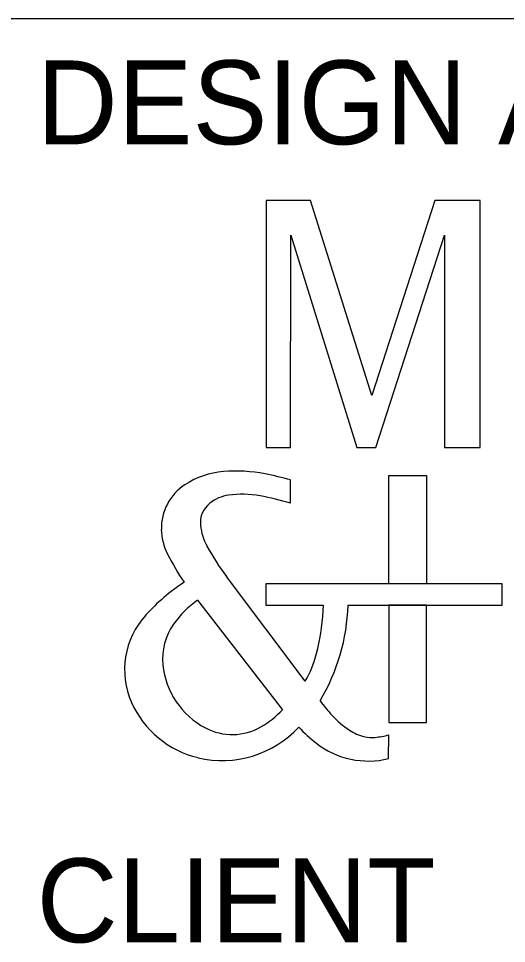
# Model space of a CAD drawing. Extents: x 0 to 34, y 0 to 22.
# Drawn here: x 32.028 to 32.61, y 3.397 to 4.5 of the extents above; entities that cross this region are included whole.
import ezdxf

# ---------------------------------------------------------------- set-up
doc = ezdxf.new("R2010")
doc.units = 0
for name, color, linetype in [('SH_Border', 7, 'Continuous'), ('SH_Data', 7, 'Continuous'), ('SH_Text', 7, 'Continuous')]:
    doc.layers.add(name, color=color, linetype=linetype)

msp = doc.modelspace()

# ---------------------------------------------------------------- linework, layer by layer
at = {"layer": 'SH_Border'}
msp.add_line((32, 4.5), (33.5, 4.5), dxfattribs=at)
at = {"layer": 'SH_Data'}
for p, q in [((32.3525, 3.922), (32.3525, 3.9497)), ((32.4696, 3.8261), (32.4697, 3.9552)), ((32.4697, 3.9552), (32.5147, 3.9552)), ((32.5147, 3.9552), (32.5146, 3.8261)), ((32.37, 3.7101), (32.2762, 3.8349)), ((32.2416, 3.8065), (32.3429, 3.6759)), ((32.4696, 3.8006), (32.4696, 3.6605)), ((32.5146, 3.8006), (32.4696, 3.8006)), ((32.5145, 3.6605), (32.5146, 3.8006)), ((32.1797, 3.7884), (32.18, 3.7887)), ((32.4696, 3.6605), (32.5145, 3.6605)), ((32.4694, 3.6176), (32.4695, 3.646))]:
    msp.add_line(p, q, dxfattribs=at)
msp.add_lwpolyline([(32.3526, 3.9885), (32.3527, 4.2417), (32.4317, 3.9885), (32.4542, 3.9885), (32.536, 4.2417), (32.5359, 3.9885), (32.5784, 3.9885), (32.5785, 4.2831), (32.5246, 4.2831), (32.4495, 4.0504), (32.3765, 4.2832), (32.3235, 4.2832), (32.3234, 3.9886)], close=True, dxfattribs=at)
msp.add_lwpolyline([(32.3526, 3.9885), (32.3527, 4.2417), (32.4317, 3.9885), (32.4542, 3.9885), (32.536, 4.2417), (32.5359, 3.9885), (32.5784, 3.9885), (32.5785, 4.2831), (32.5246, 4.2831), (32.4495, 4.0504), (32.3765, 4.2832), (32.3235, 4.2832), (32.3234, 3.9886)], close=True, dxfattribs=at)
msp.add_lwpolyline([(32.4211, 3.8006), (32.6049, 3.8006), (32.6049, 3.8261), (32.3233, 3.8261), (32.3233, 3.8007), (32.3916, 3.8006)], dxfattribs=at)
for centre, radius, start, end in [((32.2803, 3.862), 0.0981, 94.5206, 123.1061), ((32.2871, 3.7753), 0.1851, 79.0563, 94.5206), ((32.2546, 3.6069), 0.3566, 74.0516, 79.0563), ((32.2606, 3.8922), 0.062, 123.1061, 181.2152), ((32.2855, 3.8851), 0.0471, 98.3723, 128.329), ((32.2951, 3.8196), 0.1132, 79.2666, 98.3723), ((32.2495, 3.579), 0.3581, 73.2803, 79.2666), ((32.2746, 3.8989), 0.0295, 128.329, 186.0821), ((32.3115, 3.9028), 0.0666, 186.0821, 208.5769), ((32.2669, 3.8924), 0.0684, 181.2152, 207.1091), ((32.517, 4.0204), 0.3493, 207.1091, 213.4656), ((32.5116, 4.0118), 0.2945, 208.5769, 216.933), ((32.3628, 3.6213), 0.2479, 123.6, 137.6035), ((32.3108, 3.7092), 0.1194, 125.3927, 144.9042), ((32.1831, 3.8084), 0.2382, 329.2356, 358.1314), ((32.2512, 3.7236), 0.0964, 137.6035, 203.9313), ((32.2717, 3.7366), 0.0717, 144.9042, 185.7554), ((32.2959, 3.7391), 0.096, 185.7554, 242.1528), ((32.2691, 3.7316), 0.116, 203.9313, 256.6813), ((32.5828, 3.8332), 0.2441, 216.933, 222.2898), ((32.2633, 3.7491), 0.1081, 299.979, 317.3992), ((32.4823, 3.7418), 0.1082, 222.2898, 236.5762), ((32.271, 3.7399), 0.1246, 256.6813, 317.1089), ((32.2831, 3.7148), 0.0685, 242.1528, 299.979), ((32.487, 3.7702), 0.1697, 222.685, 232.3525), ((32.453, 3.6975), 0.0551, 236.5762, 256.9728), ((32.4497, 3.6832), 0.0405, 256.9728, 275.0638), ((32.446, 3.7257), 0.0831, 275.0638, 286.4619), ((32.4453, 3.7161), 0.1014, 232.3525, 283.7629)]:
    msp.add_arc(centre, radius, start, end, dxfattribs=at)
msp.add_ellipse((32.351, 3.8018), major_axis=(-0.0031, -0.1077), ratio=0.377453, start_param=0.562501, end_param=1.570796, dxfattribs=at)

# ---------------------------------------------------------------- texts
msp.add_text('DESIGN AGENCY', height=0.1, dxfattribs=at).set_placement((32.05, 4.35))
at = {"layer": 'SH_Text'}
msp.add_text('CLIENT', height=0.1, dxfattribs=at).set_placement((32.05, 3.3986))

doc.saveas('drawing.dxf')
